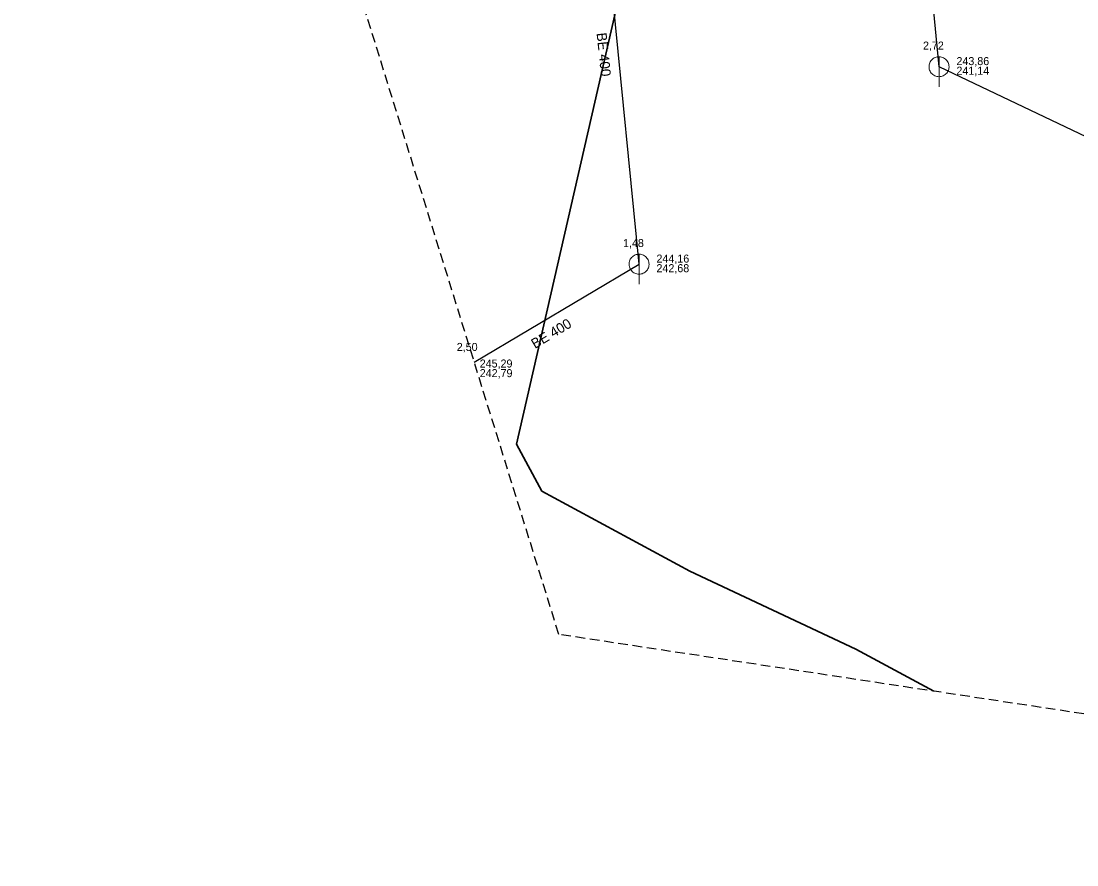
# Model space of a CAD drawing. Extents: x -777996 to -777727, y -976581 to -976199.
# Drawn here: x -777995.4 to -777889.9, y -976581.2 to -976496.9 of the extents above; entities that cross this region are included whole.
import ezdxf

# ---------------------------------------------------------------- set-up
doc = ezdxf.new("R2010")
doc.units = 0
doc.header["$LTSCALE"] = 0.32
doc.linetypes.add('MEDIUM_DASHED', pattern=[4.5, 3, -1.5])
for name, color, linetype, lineweight in [('1', 7, 'MEDIUM_DASHED', 25), ('14', 7, 'Continuous', 25), ('17', 7, 'Continuous', 25), ('22', 7, 'Continuous', 13)]:
    doc.layers.add(name, color=color, linetype=linetype, lineweight=lineweight)

msp = doc.modelspace()

# ---------------------------------------------------------------- linework, layer by layer
at = {"layer": '1'}
msp.add_lwpolyline([(-777995.417, -976203.033), (-777848.18, -976198.846), (-777864.927, -976230.247), (-777726.762, -976491.225), (-777789.565, -976581.242), (-777941.686, -976558.215), (-777989.136, -976405.396)], close=True, dxfattribs=at)
at = {"layer": '14'}
for p, q in [((-777933.671, -976521.223), (-777937.634, -976480.646)), ((-777903.695, -976501.491), (-777905.603, -976481.009)), ((-777859.114, -976522.743), (-777903.695, -976501.491)), ((-777950.137, -976530.996), (-777933.671, -976521.223))]:
    msp.add_line(p, q, dxfattribs=at)
at = {"layer": '17', "lineweight": 35}
msp.add_lwpolyline([(-777904.212, -976563.887), (-777912, -976559.699), (-777928.6, -976551.899), (-777943.399, -976543.899), (-777945.899, -976539.199), (-777934, -976487.1), (-777919.8, -976463.1), (-777903.899, -976437), (-777908, -976421.399), (-777910, -976398.3), (-777913.399, -976312.399), (-777914.899, -976265.1)], dxfattribs=at)
at = {"layer": '22'}
for p, q in [((-777903.696, -976503.491), (-777903.695, -976500.491)), ((-777933.671, -976523.223), (-777933.67, -976520.223))]:
    msp.add_line(p, q, dxfattribs=at)
for points in [[(-777902.696, -976501.491), (-777902.701, -976501.382), (-777902.719, -976501.274), (-777902.749, -976501.168), (-777902.789, -976501.067), (-777902.841, -976500.97), (-777902.903, -976500.88), (-777902.975, -976500.797), (-777903.055, -976500.723), (-777903.143, -976500.657), (-777903.237, -976500.602), (-777903.337, -976500.557), (-777903.442, -976500.524), (-777903.549, -976500.502), (-777903.658, -976500.492), (-777903.768, -976500.494), (-777903.876, -976500.508), (-777903.983, -976500.533), (-777904.086, -976500.57), (-777904.184, -976500.619), (-777904.276, -976500.677), (-777904.362, -976500.746), (-777904.439, -976500.823), (-777904.508, -976500.909), (-777904.567, -976501.001), (-777904.615, -976501.099), (-777904.652, -976501.202), (-777904.678, -976501.309), (-777904.692, -976501.417), (-777904.695, -976501.527), (-777904.685, -976501.636), (-777904.664, -976501.743), (-777904.63, -976501.847), (-777904.586, -976501.947), (-777904.531, -976502.042), (-777904.465, -976502.13), (-777904.391, -976502.21), (-777904.308, -976502.282), (-777904.218, -976502.344), (-777904.122, -976502.396), (-777904.02, -976502.437), (-777903.915, -976502.467), (-777903.807, -976502.485), (-777903.697, -976502.491), (-777903.588, -976502.485), (-777903.48, -976502.467), (-777903.375, -976502.438), (-777903.273, -976502.397), (-777903.176, -976502.345), (-777903.086, -976502.283), (-777903.003, -976502.212), (-777902.928, -976502.132), (-777902.863, -976502.044), (-777902.807, -976501.95), (-777902.763, -976501.85), (-777902.729, -976501.746), (-777902.707, -976501.638), (-777902.697, -976501.529)], [(-777932.671, -976521.223), (-777932.676, -976521.114), (-777932.694, -976521.006), (-777932.724, -976520.9), (-777932.764, -976520.799), (-777932.816, -976520.702), (-777932.878, -976520.612), (-777932.95, -976520.529), (-777933.03, -976520.455), (-777933.118, -976520.389), (-777933.212, -976520.334), (-777933.312, -976520.289), (-777933.417, -976520.256), (-777933.524, -976520.234), (-777933.633, -976520.224), (-777933.743, -976520.226), (-777933.851, -976520.24), (-777933.958, -976520.265), (-777934.061, -976520.302), (-777934.159, -976520.351), (-777934.251, -976520.409), (-777934.337, -976520.478), (-777934.414, -976520.555), (-777934.483, -976520.641), (-777934.542, -976520.733), (-777934.59, -976520.831), (-777934.627, -976520.934), (-777934.653, -976521.041), (-777934.667, -976521.149), (-777934.67, -976521.259), (-777934.66, -976521.368), (-777934.639, -976521.475), (-777934.605, -976521.579), (-777934.561, -976521.679), (-777934.506, -976521.774), (-777934.44, -976521.862), (-777934.366, -976521.942), (-777934.283, -976522.014), (-777934.193, -976522.076), (-777934.097, -976522.128), (-777933.995, -976522.169), (-777933.89, -976522.199), (-777933.782, -976522.217), (-777933.672, -976522.223), (-777933.563, -976522.217), (-777933.455, -976522.199), (-777933.35, -976522.17), (-777933.248, -976522.129), (-777933.151, -976522.077), (-777933.061, -976522.015), (-777932.978, -976521.944), (-777932.903, -976521.864), (-777932.838, -976521.776), (-777932.782, -976521.682), (-777932.738, -976521.582), (-777932.704, -976521.478), (-777932.682, -976521.37), (-777932.672, -976521.261)]]:
    msp.add_lwpolyline(points, close=True, dxfattribs=at)

# ---------------------------------------------------------------- texts
at = {"layer": '1'}
for rotation, p in [(276, (-777937.919, -976498.14)), (31, (-777944.068, -976529.703))]:
    msp.add_text('BE 400', height=1, rotation=rotation, dxfattribs=at).set_placement(p)
for s, p in [('2,72', (-777905.296, -976499.779)), ('1,48', (-777935.27, -976519.511)), ('2,50', (-777951.883, -976529.89))]:
    msp.add_text(s, height=0.8, dxfattribs=at).set_placement(p)
at = {"layer": '22'}
for s, p in [('243,86', (-777901.953, -976501.331)), ('241,14', (-777901.953, -976502.291)), ('244,16', (-777931.928, -976521.062)), ('242,68', (-777931.928, -976522.022)), ('245,29', (-777949.591, -976531.547)), ('242,79', (-777949.591, -976532.507))]:
    msp.add_text(s, height=0.8, dxfattribs=at).set_placement(p)

doc.saveas('drawing.dxf')
